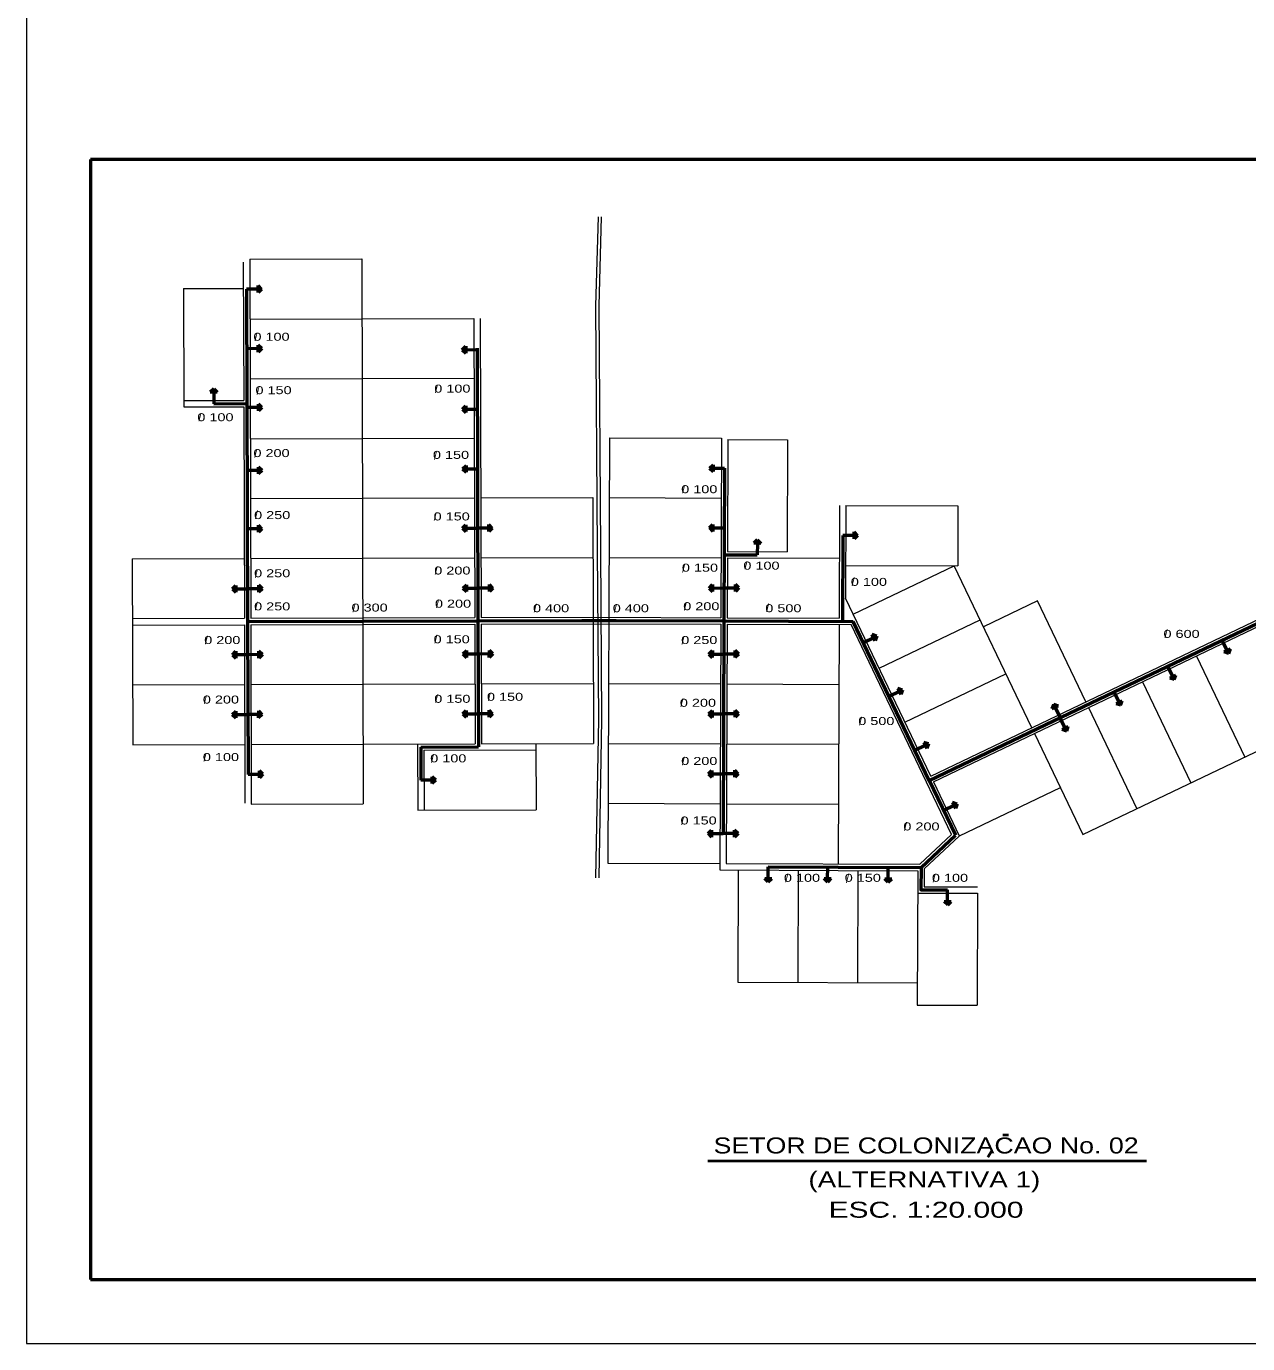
# Model space of a CAD drawing. Extents: x 312964 to 351929, y 9004151 to 9034973.
# Drawn here: x 334316 to 338132, y 9013732 to 9017848 of the extents above; entities that cross this region are included whole.
import ezdxf
from ezdxf.enums import TextEntityAlignment as Align

# ---------------------------------------------------------------- set-up
doc = ezdxf.new("R2010")
doc.units = 0
doc.header["$LTSCALE"] = 10
for name, color, linetype, lineweight in [('1', 7, 'Continuous', 13), ('2', 7, 'Continuous', 53), ('6', 7, 'Continuous', 13)]:
    doc.layers.add(name, color=color, linetype=linetype, lineweight=lineweight)

msp = doc.modelspace()

# ---------------------------------------------------------------- linework, layer by layer
at = {"layer": '1', "lineweight": 53}
for p, q in [((340056.19, 9017432.19), (334516.19, 9017432.19)), ((334516.19, 9017432.19), (334516.19, 9013932.19)), ((334516.19, 9013932.19), (340056.19, 9013932.19))]:
    msp.add_line(p, q, dxfattribs=at)
at = {"layer": '1'}
for p, q in [((334994.09, 9017111.45), (334995.37, 9016679.51)), ((335014.07, 9017120.56), (335364.06, 9017121.6)), ((335014.07, 9017120.56), (335017.39, 9015998.57)), ((335364.06, 9017121.6), (335369.1, 9015418.61)), ((334807.34, 9017028.95), (334994.34, 9017029.51)), ((334807.34, 9017028.95), (334808.43, 9016658.95)), ((335014.62, 9016933.56), (335364.62, 9016934.6)), ((335364.62, 9016934.6), (335714.62, 9016935.64)), ((335714.62, 9016935.64), (335717.38, 9016000.64)), ((335734.62, 9016935.7), (335737.38, 9016000.7)), ((335015.17, 9016746.57), (335365.17, 9016747.6)), ((335365.17, 9016747.6), (335715.17, 9016748.64)), ((334808.37, 9016678.95), (334995.37, 9016679.51)), ((334808.43, 9016658.95), (334995.43, 9016659.51)), ((334995.43, 9016659.51), (334997.39, 9015998.51)), ((335015.73, 9016559.57), (335365.72, 9016560.6)), ((335365.72, 9016560.6), (335715.72, 9016561.64)), ((336138.12, 9016562.71), (336133.09, 9015233.72)), ((336138.12, 9016562.71), (336488.12, 9016561.39)), ((336488.12, 9016561.39), (336485.99, 9016000.39)), ((336508.1, 9016557.31), (336506.78, 9016207.32)), ((335016.28, 9016372.57), (335366.28, 9016373.6)), ((335366.28, 9016373.6), (335716.28, 9016374.64)), ((335736.28, 9016374.7), (336086.27, 9016375.73)), ((336086.27, 9016375.73), (336088.55, 9015607.74)), ((336137.41, 9016375.72), (336487.41, 9016374.39)), ((336857.33, 9016351.13), (336855.99, 9015998.99)), ((336877.33, 9016351.05), (336876.23, 9016061.47)), ((337142.16, 9015505.65), (338717.49, 9016259.37)), ((334646.83, 9016184.47), (334996.83, 9016185.51)), ((334646.83, 9016184.47), (334648.55, 9015603.48)), ((335736.83, 9016187.7), (336086.83, 9016188.73)), ((336136.71, 9016188.72), (336486.7, 9016187.39)), ((336506.7, 9016187.32), (336505.99, 9016000.32)), ((336506.7, 9016187.32), (336856.7, 9016185.99)), ((336506.78, 9016207.32), (336693.78, 9016206.61)), ((336876.62, 9016164.05), (337226.61, 9016162.73)), ((336900.03, 9016011.71), (337215.76, 9016162.77)), ((337457.88, 9015656.71), (337215.76, 9016162.77)), ((337142.16, 9015505.65), (336876.23, 9016061.47)), ((337150.79, 9015487.61), (338309.95, 9016042.21)), ((334647.39, 9015997.47), (334997.39, 9015998.51)), ((334647.45, 9015977.47), (334997.44, 9015978.51)), ((334997.44, 9015978.51), (334999.09, 9015421.45)), ((335017.39, 9015998.57), (335717.38, 9016000.64)), ((335017.44, 9015978.57), (335717.44, 9015980.64)), ((335017.44, 9015978.57), (335019.1, 9015417.57)), ((335717.44, 9015980.64), (335718.55, 9015606.64)), ((335737.38, 9016000.7), (336112.38, 9016001.81)), ((335737.44, 9015980.7), (336112.37, 9015981.81)), ((335737.44, 9015980.7), (335738.55, 9015606.7)), ((336112.37, 9015981.81), (336485.92, 9015980.39)), ((336112.38, 9016001.81), (336485.99, 9016000.39)), ((336485.92, 9015980.39), (336483.01, 9015212.4)), ((336505.92, 9015980.32), (336503.09, 9015232.32)), ((336505.92, 9015980.32), (336893.59, 9015978.85)), ((336505.99, 9016000.32), (336855.99, 9015998.99)), ((336855.92, 9015978.99), (336853.08, 9015231)), ((337207.23, 9015323.3), (336893.59, 9015978.85)), ((336980.74, 9015843.03), (337296.47, 9015994.08)), ((337972.57, 9015880.79), (338123.63, 9015565.07)), ((337061.45, 9015674.34), (337377.17, 9015825.4)), ((334648, 9015790.48), (334998, 9015791.51)), ((335018, 9015791.57), (335717.99, 9015793.64)), ((335737.99, 9015793.7), (336087.99, 9015794.74)), ((336135.21, 9015794.72), (336485.21, 9015793.39)), ((336505.21, 9015793.32), (336855.21, 9015791.99)), ((337803.89, 9015800.08), (337954.95, 9015484.36)), ((337635.2, 9015719.38), (337786.26, 9015403.65)), ((334648.55, 9015603.48), (334998.55, 9015604.51)), ((335018.55, 9015604.57), (335718.55, 9015606.64)), ((335538.55, 9015606.11), (335539.16, 9015399.11)), ((335738.55, 9015606.7), (336088.55, 9015607.74)), ((335908.55, 9015607.2), (335909.16, 9015400.2)), ((336134.5, 9015607.72), (336484.5, 9015606.4)), ((336504.5, 9015606.32), (336854.5, 9015604.99)), ((335558.61, 9015586.17), (335908.61, 9015587.2)), ((335558.61, 9015586.17), (335559.16, 9015399.17)), ((337150.79, 9015487.61), (337231.5, 9015318.92)), ((337232.1, 9015319.21), (337547.22, 9015469.98)), ((335019.1, 9015417.57), (335369.1, 9015418.61)), ((335539.16, 9015399.11), (335909.16, 9015400.2)), ((336133.8, 9015420.72), (336483.79, 9015419.4)), ((336503.79, 9015419.32), (336853.79, 9015418)), ((337107.88, 9015230.03), (337207.23, 9015323.3)), ((337121.81, 9015215.67), (337232.1, 9015319.21)), ((336133.09, 9015233.72), (336483.09, 9015232.4)), ((336483.01, 9015212.4), (336853.01, 9015211)), ((336503.09, 9015232.32), (337107.88, 9015230.03)), ((336540.79, 9015212.18), (336539.46, 9014862.18)), ((336727.79, 9015211.47), (336726.46, 9014861.47)), ((336853.01, 9015211), (337101.79, 9015210.06)), ((336914.79, 9015210.76), (336913.46, 9014860.77)), ((337101.79, 9015210.06), (337100.2, 9014790.06)), ((337121.81, 9015215.67), (337121.6, 9015159.98)), ((337121.6, 9015159.98), (337288.6, 9015159.35)), ((337101.52, 9015140.06), (337288.52, 9015139.35)), ((337288.52, 9015139.35), (337287.19, 9014789.35)), ((336539.46, 9014862.18), (337100.46, 9014860.06)), ((337100.2, 9014790.06), (337287.19, 9014789.35))]:
    msp.add_line(p, q, dxfattribs=at)
at = {"layer": '1', "lineweight": 40}
for p, q in [((337367.23, 9014384.76), (337385.52, 9014384.76)), ((337333.25, 9014334.92), (337320.59, 9014315.22)), ((336445.82, 9014303.53), (337816.35, 9014303.53))]:
    msp.add_line(p, q, dxfattribs=at)
at = {"layer": '1'}
msp.add_lwpolyline([(340256.19, 9017932.19), (334316.19, 9017932.19), (334316.19, 9013732.19), (340256.19, 9013732.19)], close=True, dxfattribs=at)
for points in [[(336508.1, 9016557.31), (336695.1, 9016556.61), (336693.78, 9016206.61)], [(336877.33, 9016351.05), (337227.32, 9016349.73), (337226.61, 9016162.73)], [(335016.83, 9016185.57), (335366.83, 9016186.6), (335716.83, 9016187.64)], [(337626.57, 9015737.42), (337475.51, 9016053.14), (337306.82, 9015972.43)], [(337466.51, 9015638.67), (337617.57, 9015322.94), (338461.01, 9015726.48)]]:
    msp.add_lwpolyline(points, dxfattribs=at)
at = {"layer": '2'}
for p, q in [((335004.34, 9017027.04), (335007.42, 9015988.54)), ((335040.19, 9017026.91), (335004.34, 9017027.04)), ((335040.16, 9017016.39), (335040.23, 9017037.95)), ((335050.97, 9017027.14), (335040.16, 9017016.39)), ((335050.97, 9017027.14), (335040.23, 9017037.95)), ((335040.74, 9016840.98), (335004.89, 9016841.1)), ((335040.71, 9016830.46), (335040.78, 9016852.02)), ((335051.52, 9016841.2), (335040.71, 9016830.46)), ((335051.52, 9016841.2), (335040.78, 9016852.02)), ((335678.28, 9016837.83), (335689.09, 9016848.58)), ((335689.09, 9016848.58), (335689.02, 9016827.02)), ((335678.28, 9016837.83), (335689.02, 9016827.02)), ((335689.06, 9016838.06), (335724.91, 9016837.94)), ((334901.8, 9016715.86), (334890.98, 9016705.12)), ((334901.8, 9016715.86), (334912.54, 9016705.04)), ((334912.54, 9016705.04), (334890.98, 9016705.12)), ((334902.02, 9016705.08), (334901.9, 9016669.23)), ((334901.9, 9016669.23), (335005.4, 9016669.54)), ((335041.29, 9016656.95), (335005.44, 9016657.07)), ((335041.25, 9016646.43), (335041.32, 9016667.98)), ((335052.07, 9016657.17), (335041.25, 9016646.43)), ((335052.07, 9016657.17), (335041.32, 9016667.98)), ((335678.83, 9016651.99), (335689.64, 9016662.73)), ((335678.83, 9016651.99), (335689.57, 9016641.17)), ((335689.64, 9016662.73), (335689.57, 9016641.17)), ((335689.61, 9016652.21), (335725.46, 9016652.09)), ((335041.83, 9016449.63), (335041.9, 9016471.19)), ((335052.65, 9016460.37), (335041.9, 9016471.19)), ((335679.38, 9016465.7), (335690.19, 9016476.45)), ((335690.19, 9016476.45), (335690.12, 9016454.89)), ((336451.14, 9016467.75), (336461.95, 9016478.49)), ((336461.95, 9016478.49), (336461.88, 9016456.93)), ((335041.87, 9016460.15), (335006.02, 9016460.27)), ((335052.65, 9016460.37), (335041.83, 9016449.63)), ((335679.38, 9016465.7), (335690.12, 9016454.89)), ((335690.16, 9016465.93), (335726.01, 9016465.81)), ((336451.14, 9016467.75), (336461.88, 9016456.93)), ((336461.92, 9016467.97), (336497.77, 9016467.85)), ((336497.77, 9016467.85), (336495.96, 9015990.36)), ((335041.3, 9016278.12), (335005.45, 9016278.24)), ((335041.27, 9016267.6), (335041.34, 9016289.16)), ((335052.08, 9016278.34), (335041.27, 9016267.6)), ((335052.08, 9016278.34), (335041.34, 9016289.16)), ((335678.82, 9016280.27), (335689.64, 9016291.01)), ((335678.82, 9016280.27), (335689.56, 9016269.45)), ((335689.64, 9016291.01), (335689.56, 9016269.45)), ((335689.6, 9016280.49), (335725.45, 9016280.37)), ((335761.3, 9016280.25), (335725.45, 9016280.37)), ((335761.26, 9016269.73), (335761.33, 9016291.29)), ((335772.08, 9016280.47), (335761.26, 9016269.73)), ((335772.08, 9016280.47), (335761.33, 9016291.29)), ((336450.43, 9016280.83), (336461.24, 9016291.57)), ((336450.43, 9016280.83), (336461.17, 9016270.01)), ((336461.24, 9016291.57), (336461.17, 9016270.01)), ((336461.21, 9016281.05), (336497.06, 9016280.93)), ((336902.78, 9016246.95), (336902.86, 9016268.51)), ((336913.6, 9016257.69), (336902.86, 9016268.51)), ((336600.14, 9016243.59), (336589.32, 9016232.85)), ((336610.88, 9016232.77), (336589.32, 9016232.85)), ((336600.14, 9016243.59), (336610.88, 9016232.77)), ((336600.36, 9016232.81), (336600.24, 9016196.96)), ((336866.97, 9016257.59), (336865.95, 9015988.95)), ((336902.82, 9016257.47), (336866.97, 9016257.59)), ((336913.6, 9016257.69), (336902.78, 9016246.95)), ((337975.08, 9015893.07), (338721.81, 9016250.35)), ((336496.74, 9016197.35), (336600.24, 9016196.96)), ((334960.48, 9016090.68), (334971.3, 9016101.42)), ((334971.3, 9016101.42), (334971.23, 9016079.86)), ((335042.93, 9016080.14), (335043, 9016101.7)), ((335053.74, 9016090.88), (335043, 9016101.7)), ((335680.48, 9016092.81), (335691.3, 9016103.55)), ((335691.3, 9016103.55), (335691.22, 9016081.99)), ((335762.92, 9016082.27), (335762.99, 9016103.83)), ((335773.74, 9016093.01), (335762.99, 9016103.83)), ((336449.72, 9016093.15), (336460.53, 9016103.89)), ((336460.53, 9016103.89), (336460.46, 9016082.34)), ((336532.16, 9016082.61), (336532.23, 9016104.17)), ((336542.97, 9016093.35), (336532.23, 9016104.17)), ((334960.48, 9016090.68), (334971.23, 9016079.86)), ((334971.26, 9016090.9), (335007.11, 9016090.78)), ((335042.96, 9016090.66), (335007.11, 9016090.78)), ((335053.74, 9016090.88), (335042.93, 9016080.14)), ((335680.48, 9016092.81), (335691.22, 9016081.99)), ((335691.26, 9016093.03), (335727.11, 9016092.91)), ((335762.96, 9016092.79), (335727.11, 9016092.91)), ((335773.74, 9016093.01), (335762.92, 9016082.27)), ((336449.72, 9016093.15), (336460.46, 9016082.34)), ((336460.5, 9016093.37), (336496.35, 9016093.25)), ((336532.19, 9016093.13), (336496.35, 9016093.25)), ((336542.97, 9016093.35), (336532.16, 9016082.61)), ((335007.42, 9015988.54), (335727.41, 9015990.67)), ((335007.42, 9015988.54), (335008.83, 9015511.04)), ((335727.41, 9015990.67), (336052.14, 9015991.63)), ((336052.14, 9015991.63), (336112.41, 9015991.81)), ((336495.96, 9015990.36), (336493.44, 9015325.86)), ((336495.96, 9015990.36), (336899.9, 9015988.83)), ((337137.45, 9015492.31), (336899.9, 9015988.83)), ((336963.97, 9015937.98), (336931.68, 9015922.4)), ((336968.54, 9015928.5), (336959.17, 9015947.92)), ((336973.56, 9015942.89), (336959.17, 9015947.92)), ((336973.56, 9015942.89), (336968.54, 9015928.5)), ((334960.39, 9015884.94), (334971.21, 9015895.68)), ((334971.21, 9015895.68), (334971.14, 9015874.12)), ((335042.84, 9015874.4), (335042.91, 9015895.96)), ((335053.65, 9015885.14), (335042.91, 9015895.96)), ((335680.39, 9015887.07), (335691.21, 9015897.81)), ((335691.21, 9015897.81), (335691.13, 9015876.25)), ((335762.83, 9015876.53), (335762.91, 9015898.09)), ((335773.65, 9015887.27), (335762.91, 9015898.09)), ((336448.94, 9015886.75), (336459.75, 9015897.5)), ((336459.75, 9015897.5), (336459.68, 9015875.94)), ((336531.38, 9015876.22), (336531.45, 9015897.77)), ((336542.19, 9015886.96), (336531.45, 9015897.77)), ((338068.76, 9015898.16), (338053.18, 9015930.44)), ((338059.28, 9015893.58), (338078.7, 9015902.95)), ((338073.68, 9015888.56), (338059.28, 9015893.58)), ((338073.68, 9015888.56), (338078.7, 9015902.95)), ((334960.39, 9015884.94), (334971.14, 9015874.12)), ((334971.17, 9015885.16), (335007.02, 9015885.04)), ((335042.87, 9015884.92), (335007.02, 9015885.04)), ((335053.65, 9015885.14), (335042.84, 9015874.4)), ((335680.39, 9015887.07), (335691.13, 9015876.25)), ((335691.17, 9015887.29), (335727.02, 9015887.17)), ((335762.87, 9015887.05), (335727.02, 9015887.17)), ((335773.65, 9015887.27), (335762.83, 9015876.53)), ((336448.94, 9015886.75), (336459.68, 9015875.94)), ((336459.72, 9015886.98), (336495.56, 9015886.86)), ((336531.41, 9015886.74), (336495.56, 9015886.86)), ((336542.19, 9015886.96), (336531.38, 9015876.22)), ((337898.3, 9015816.6), (337882.71, 9015848.88)), ((337888.82, 9015812.03), (337908.24, 9015821.4)), ((337903.21, 9015807), (337888.82, 9015812.03)), ((337903.21, 9015807), (337908.24, 9015821.4)), ((337044.56, 9015769.53), (337012.28, 9015753.95)), ((337049.13, 9015760.05), (337039.76, 9015779.47)), ((337054.16, 9015774.45), (337039.76, 9015779.47)), ((337054.16, 9015774.45), (337049.13, 9015760.05)), ((337525.56, 9015728.55), (337521.02, 9015715.53)), ((337526.04, 9015729.92), (337525.56, 9015728.55)), ((337526.04, 9015729.92), (337540.44, 9015724.9)), ((337730.68, 9015736.4), (337715.1, 9015768.69)), ((337721.21, 9015731.83), (337740.62, 9015741.2)), ((337735.6, 9015726.81), (337721.21, 9015731.83)), ((337735.6, 9015726.81), (337740.62, 9015741.2)), ((334959.69, 9015697.94), (334970.5, 9015708.68)), ((334959.69, 9015697.94), (334970.43, 9015687.12)), ((334970.5, 9015708.68), (334970.43, 9015687.12)), ((334970.47, 9015698.16), (335006.31, 9015698.04)), ((335042.16, 9015697.92), (335006.31, 9015698.04)), ((335042.13, 9015687.4), (335042.2, 9015708.96)), ((335052.94, 9015698.14), (335042.13, 9015687.4)), ((335052.94, 9015698.14), (335042.2, 9015708.96)), ((335679.68, 9015700.07), (335690.5, 9015710.81)), ((335679.68, 9015700.07), (335690.43, 9015689.25)), ((335690.5, 9015710.81), (335690.43, 9015689.25)), ((335690.46, 9015700.29), (335726.31, 9015700.17)), ((335762.16, 9015700.05), (335726.31, 9015700.17)), ((335762.12, 9015689.53), (335762.2, 9015711.09)), ((335772.94, 9015700.27), (335762.12, 9015689.53)), ((335772.94, 9015700.27), (335762.2, 9015711.09)), ((336448.23, 9015699.76), (336459.04, 9015710.5)), ((336448.23, 9015699.76), (336458.97, 9015688.94)), ((336459.04, 9015710.5), (336458.97, 9015688.94)), ((336459.01, 9015699.98), (336494.86, 9015699.86)), ((336530.7, 9015699.74), (336494.86, 9015699.86)), ((336530.67, 9015689.22), (336530.74, 9015710.78)), ((336541.48, 9015699.96), (336530.67, 9015689.22)), ((336541.48, 9015699.96), (336530.74, 9015710.78)), ((337525.56, 9015717.72), (337521.02, 9015715.53)), ((337540.44, 9015724.9), (337525.56, 9015717.72)), ((337530.96, 9015720.33), (337546.54, 9015688.04)), ((337562.12, 9015655.76), (337546.54, 9015688.04)), ((337552.65, 9015651.18), (337572.06, 9015660.55)), ((337567.04, 9015646.16), (337552.65, 9015651.18)), ((337567.04, 9015646.16), (337572.06, 9015660.55)), ((337129.77, 9015591.53), (337120.4, 9015610.94)), ((337134.79, 9015605.92), (337120.4, 9015610.94)), ((337134.79, 9015605.92), (337129.77, 9015591.53)), ((335548.58, 9015596.14), (335728.58, 9015596.67)), ((335548.58, 9015596.14), (335548.88, 9015492.64)), ((337125.19, 9015601), (337092.91, 9015585.42)), ((335044.64, 9015500.4), (335044.71, 9015521.96)), ((335055.46, 9015511.14), (335044.71, 9015521.96)), ((336447.52, 9015512.76), (336458.33, 9015523.5)), ((336458.33, 9015523.5), (336458.26, 9015501.94)), ((336529.96, 9015502.22), (336530.03, 9015523.78)), ((336540.78, 9015512.96), (336530.03, 9015523.78)), ((335044.68, 9015510.92), (335008.83, 9015511.04)), ((335055.46, 9015511.14), (335044.64, 9015500.4)), ((335584.73, 9015492.52), (335548.88, 9015492.64)), ((335584.7, 9015482), (335584.77, 9015503.56)), ((335595.51, 9015492.74), (335584.7, 9015482)), ((335595.51, 9015492.74), (335584.77, 9015503.56)), ((336447.52, 9015512.76), (336458.26, 9015501.94)), ((336458.3, 9015512.98), (336494.15, 9015512.86)), ((336530, 9015512.74), (336494.15, 9015512.86)), ((336540.78, 9015512.96), (336529.96, 9015502.22)), ((337137.45, 9015492.31), (337219.41, 9015321.01)), ((337214.96, 9015413.38), (337182.67, 9015397.8)), ((337219.53, 9015403.91), (337210.16, 9015423.32)), ((337224.55, 9015418.3), (337210.16, 9015423.32)), ((337224.55, 9015418.3), (337219.53, 9015403.91)), ((336446.81, 9015325.76), (336457.63, 9015336.5)), ((336446.81, 9015325.76), (336457.55, 9015314.94)), ((336457.63, 9015336.5), (336457.55, 9015314.94)), ((336457.59, 9015325.98), (336493.44, 9015325.86)), ((336529.29, 9015325.74), (336493.44, 9015325.86)), ((336529.25, 9015315.22), (336529.32, 9015336.78)), ((336540.07, 9015325.96), (336529.25, 9015315.22)), ((336540.07, 9015325.96), (336529.32, 9015336.78)), ((337111.82, 9015220.02), (337219.41, 9015321.01)), ((336634.21, 9015185.98), (336634.33, 9015221.83)), ((336820.06, 9015185.27), (336820.18, 9015221.12)), ((337009.22, 9015184.56), (337009.34, 9015220.41)), ((336623.69, 9015186.01), (336645.24, 9015185.94)), ((336634.43, 9015175.2), (336623.69, 9015186.01)), ((336634.43, 9015175.2), (336645.24, 9015185.94)), ((336809.54, 9015185.31), (336831.1, 9015185.24)), ((336820.29, 9015174.49), (336809.54, 9015185.31)), ((336820.29, 9015174.49), (336831.1, 9015185.24)), ((336998.7, 9015184.59), (337020.26, 9015184.52)), ((337009.44, 9015173.78), (336998.7, 9015184.59)), ((337009.44, 9015173.78), (337020.26, 9015184.52)), ((337184.39, 9015113.89), (337205.95, 9015113.82)), ((337195.13, 9015103.07), (337184.39, 9015113.89)), ((337194.91, 9015113.85), (337195.03, 9015149.7)), ((337195.13, 9015103.07), (337205.95, 9015113.82))]:
    msp.add_line(p, q, dxfattribs=at)
for points in [[(335724.89, 9016842.17), (335727.41, 9015990.67), (335728.58, 9015596.67)], [(336112.34, 9015991.81), (336158.97, 9015991.63), (336495.96, 9015990.36)], [(337137.45, 9015492.31), (337525.56, 9015678), (337975.08, 9015893.07)], [(336634.33, 9015221.83), (336853.04, 9015221), (337111.82, 9015220.02), (337111.56, 9015150.02), (337195.06, 9015149.7)]]:
    msp.add_lwpolyline(points, dxfattribs=at)
at = {"layer": '6'}
for p, q in [((336095.79, 9016974.89), (336103.63, 9017253.37)), ((336100.79, 9016212.54), (336095.79, 9016974.54)), ((336104.79, 9015682.53), (336100.79, 9016212.53)), ((336095.79, 9015187.79), (336104.79, 9015682.79))]:
    msp.add_line(p, q, dxfattribs=at)
msp.add_lwpolyline([(336105.79, 9015187.61), (336114.79, 9015682.61), (336110.79, 9016212.61), (336105.79, 9016974.61), (336113.63, 9017253.37)], dxfattribs=at)

# ---------------------------------------------------------------- texts
at = {"layer": '1'}
for s, width, p in [('SETOR DE COLONIZACAO No. 02', 1.25, (337127.59, 9014326.41)), ('(ALTERNATIVA 1)', 1.3, (337122.16, 9014220.29)), ('ESC. 1:20.000', 1.4, (337127.41, 9014125.65))]:
    msp.add_text(s, height=50, dxfattribs=dict(at, width=width)).set_placement(p, align=Align.CENTER)
at = {"layer": '2', "width": 1.35}
for s, p in [('0 100', (335082.29, 9016865.83)), ('0 150', (335088.63, 9016698.89)), ('0 100', (335647.39, 9016703.81)), ('0 100', (334907.03, 9016614.35)), ('0 200', (335082.29, 9016502.35)), ('0 150', (335643.17, 9016496.71)), ('0 100', (336418.96, 9016389.41)), ('0 250', (335084.39, 9016308.6)), ('0 150', (335645.28, 9016304.4)), ('0 250', (335084.39, 9016126.86)), ('0 200', (335647.39, 9016135.34)), ('0 150', (336421.07, 9016144.27)), ('0 100', (336613.22, 9016150.61)), ('0 100', (336948.96, 9016099.89)), ('0 200', (335649.5, 9016031.79)), ('0 250', (335084.39, 9016023.31)), ('0 300', (335388.81, 9016019.59)), ('0 400', (335955.87, 9016017.51)), ('0 400', (336205.04, 9016017.51)), ('0 200', (336425.29, 9016023.81)), ('0 500', (336681.7, 9016017.51)), ('0 200', (334928.49, 9015918.15)), ('0 150', (335645.25, 9015920.49)), ('0 250', (336418.96, 9015918.15)), ('0 600', (337925.94, 9015937.37)), ('0 200', (334924.26, 9015732.18)), ('0 150', (335647.36, 9015734.52)), ('0 150', (335812.06, 9015740.86)), ('0 200', (336414.75, 9015722.1)), ('0 500', (336972.17, 9015665.08)), ('0 100', (334924.26, 9015552.55)), ('0 100', (335634.69, 9015548.55)), ('0 200', (336418.97, 9015540.35)), ('0 150', (336416.86, 9015354.39)), ('0 200', (337113.12, 9015335.76)), ('0 100', (336739.91, 9015175.22)), ('0 150', (336929.95, 9015175.22)), ('0 100', (337202.34, 9015175.22))]:
    msp.add_text(s, height=25, dxfattribs=at).set_placement(p, align=Align.CENTER)
at = {"layer": '2'}
for p in [(335033.98, 9016864.89), (335040.31, 9016697.47), (335597.77, 9016702.75), (334858.72, 9016613.99), (335032.92, 9016500.93), (335594.6, 9016494.59), (336370.07, 9016389.16), (335034.93, 9016309.22), (335593.76, 9016303.85), (335034.93, 9016125.36), (335596.93, 9016134.79), (336370.07, 9016141.13), (336565.04, 9016151.7), (336899.72, 9016099.93), (335601.15, 9016031.24), (335034.93, 9016023.93), (335340.05, 9016017.59), (335906.28, 9016017.5), (336156.8, 9016016.45), (336375.35, 9016022.79), (336632.61, 9016018.57), (334878.68, 9015917.62), (335595.93, 9015920.89), (336367.95, 9015916.69), (337877.45, 9015937.66), (334875.51, 9015731.65), (335598.05, 9015734.92), (335762.75, 9015740.21), (336364.78, 9015722.26), (336922.94, 9015664.97), (334874.45, 9015551.16), (335585.38, 9015547.9), (336369.08, 9015539.91), (336366.97, 9015352.89), (337063.25, 9015335.86), (336692.15, 9015174.32), (336882.19, 9015172.2), (337152.99, 9015174.2)]:
    msp.add_text('/', height=25, dxfattribs=at).set_placement(p, align=Align.CENTER)

doc.saveas('drawing.dxf')
